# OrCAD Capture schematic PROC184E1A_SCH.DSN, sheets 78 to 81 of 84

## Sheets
78 82.CURRENT MONITORS#1 -INA231: size C; title: CURRENT MONITORS#1- INA231; note: PROC184_SCH
79 83. CURRENT MONITORS#2 -INA231: size C; title: CURRENT MONITORS#2- INA231; note: PROC184_SCH
80 84. HARDWARE SCHEMATICS: title: HARDWARE SCHEMATICS; note: PROC184_SCH
81 55. CAN TRANSCEIVER #3: size C; title: CAN TRANSCEIVER #3; note: PROC184_SCH
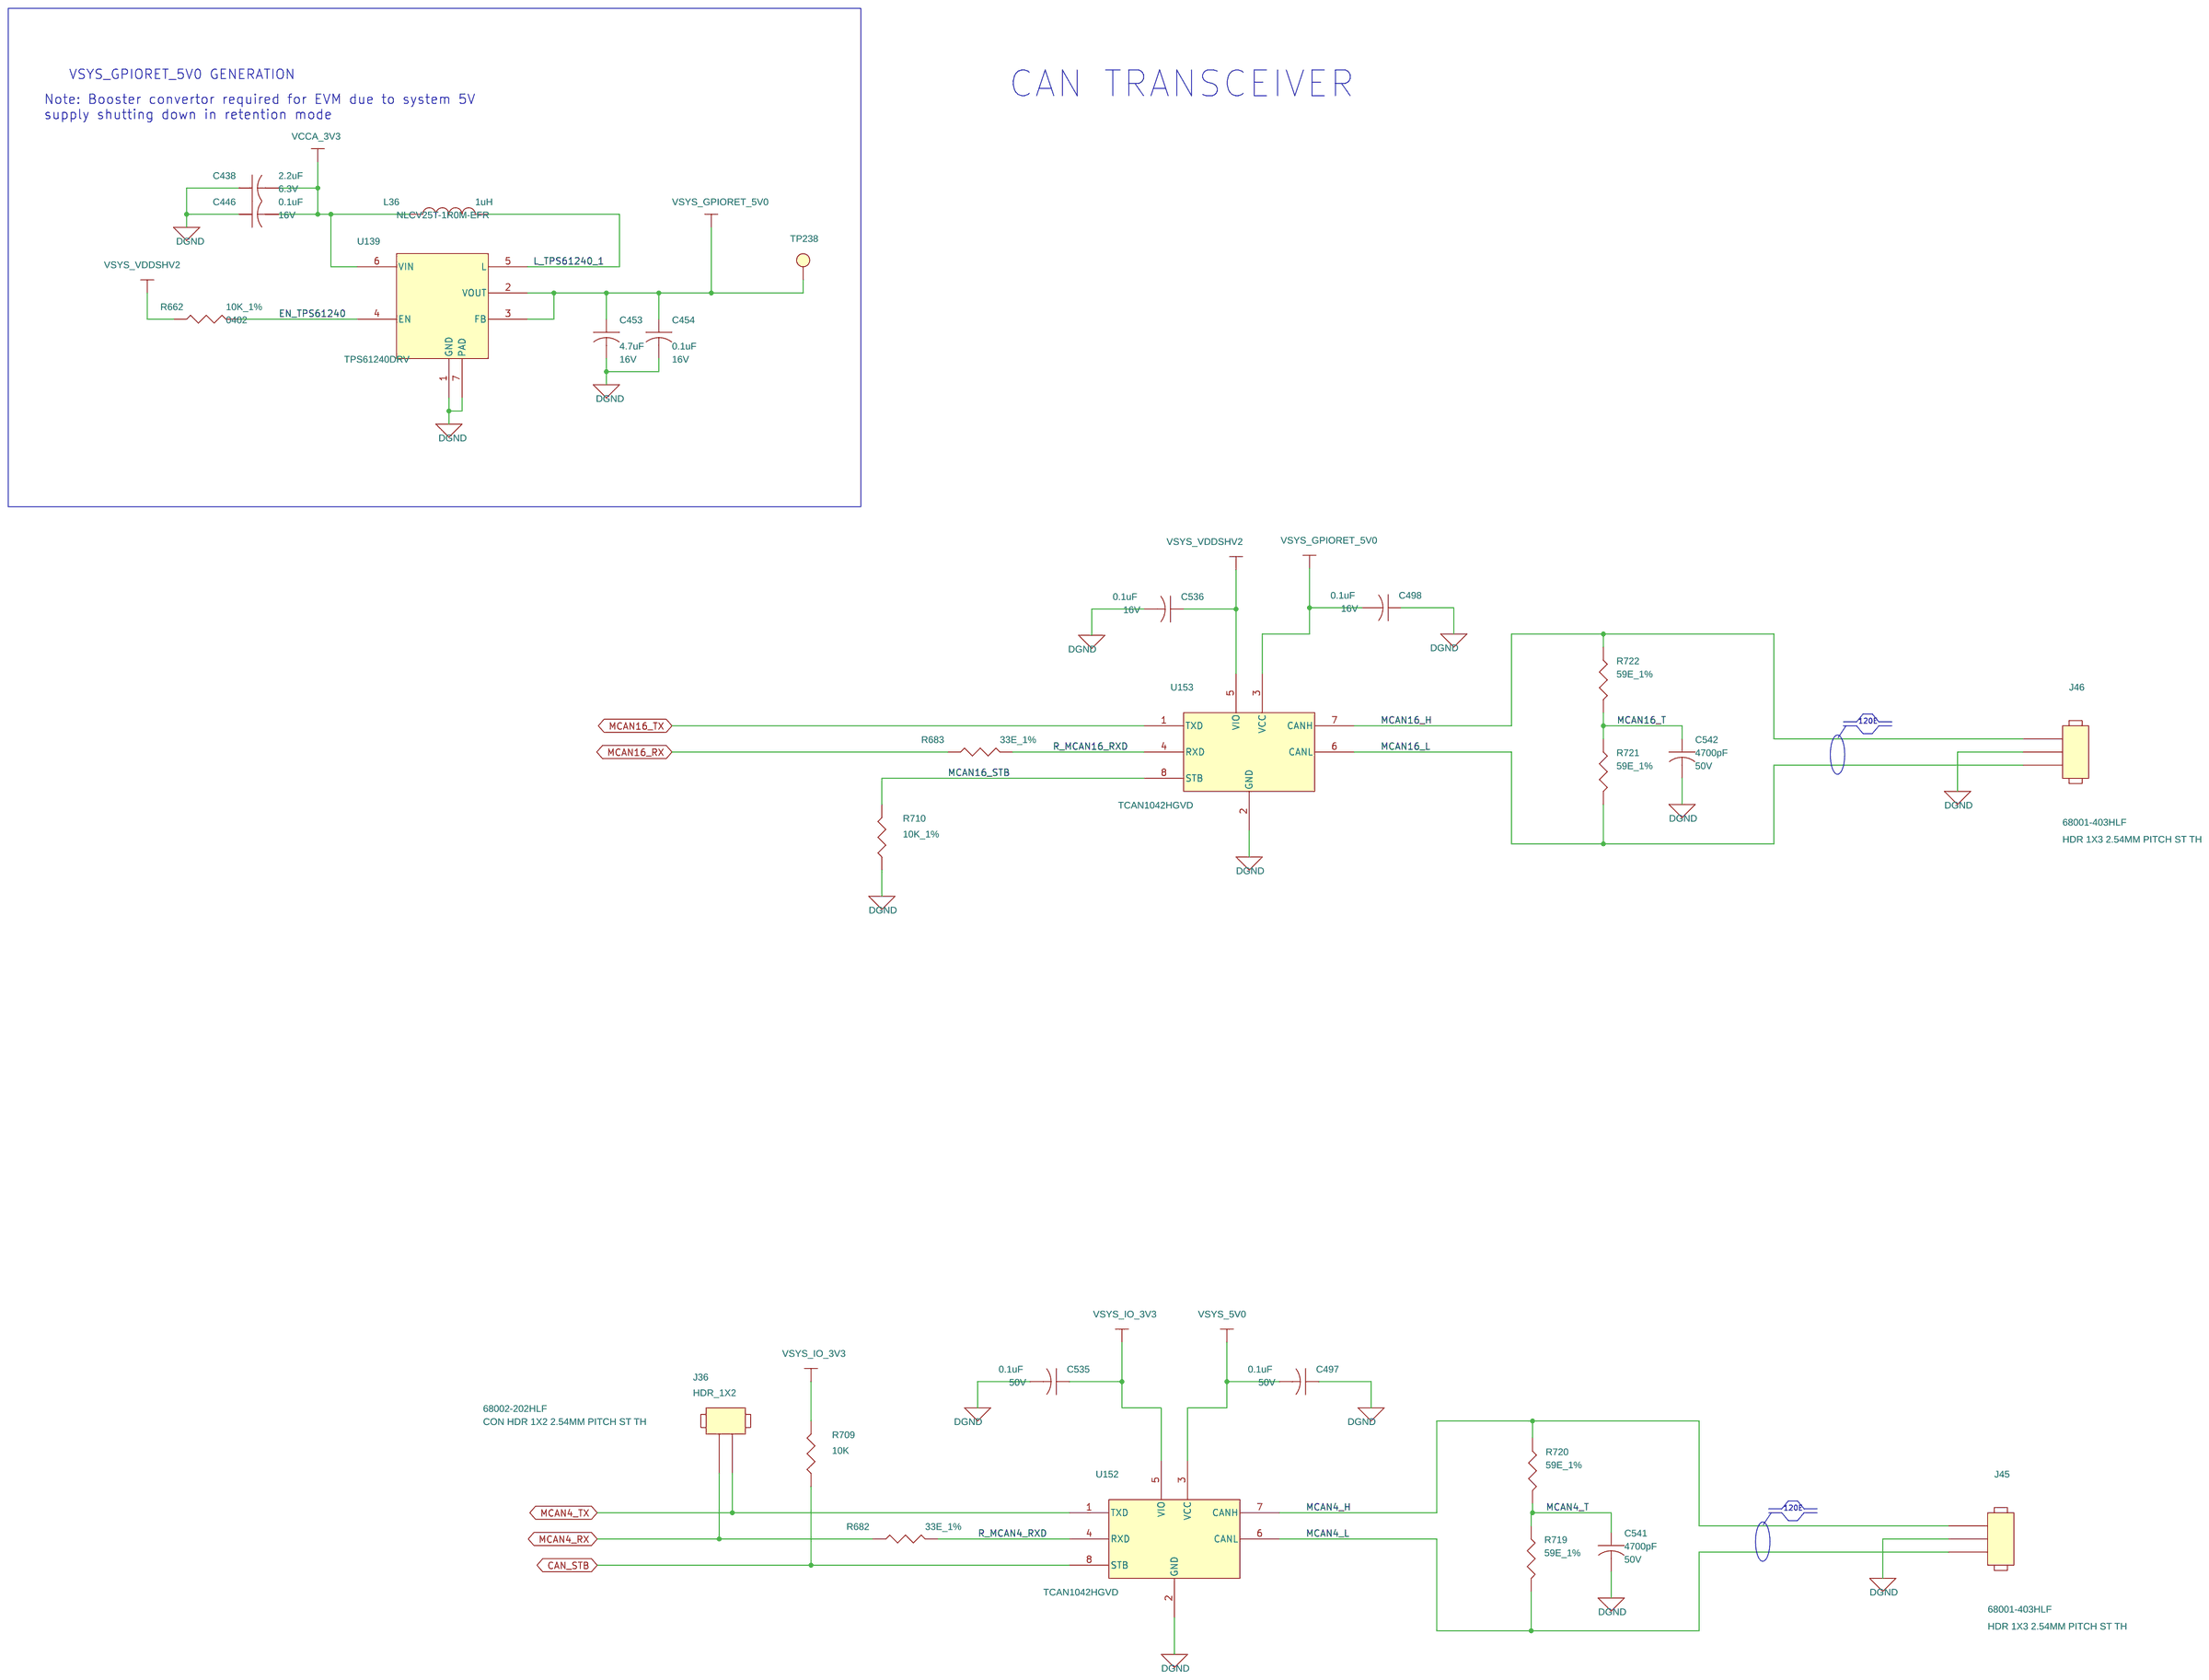
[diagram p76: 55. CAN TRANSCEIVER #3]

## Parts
sheet 55. CAN TRANSCEIVER #3
C438  2.2uF  [CAP0603_1]
C446  0.1uF  [CAP0402_0-75]
C453  4.7uF  [CAP0805_1-5]
C454  0.1uF  [CAP0402_0-75]
C497  0.1uF  [CAP0402_0-75]
C498  0.1uF  [CAP0402_0-75]
C535  0.1uF  [CAP0402_0-75]
C536  0.1uF  [CAP0402_0-75]
C541  4700pF  [CAP0402_0-75]
C542  4700pF  [CAP0402_0-75]
J36  HDR_1X2  [HDR_1X2_68002-202_S_T_8-6]
J45  HDR_1X3  [HDR_3X1_100_S_T]
J46  HDR_1X3  [HDR_3X1_100_S_T]
L36  1uH  [IND_NLCV25T-EFR_110X80_SMD_1-9]
R662  10K_1%  [RES0402_0-5]
R682  33E_1%  [RES0402_0-5]
R683  33E_1%  [RES0402_0-5]
R709  10K  [RES0402_0-5]
R710  10K_1%  [RES0402_0-5]
R719  59E_1%  [RES0402_0-5]
R720  59E_1%  [RES0402_0-5]
R721  59E_1%  [RES0402_0-5]
R722  59E_1%  [RES0402_0-5]
TP238  TP30_SMD  [TP30_SMD]
U139  TPS61240DRV  [SON6_25-59_85X85]
U152  TCAN1042HGVD  [SOIC8_1-8]
U153  TCAN1042HGVD  [SOIC8_1-8]
sheet 82.CURRENT MONITORS#1 -INA231
U61  INA231AIYFDR  [DSBGA12_15-74_60X70_0-4]
U64  INA231AIYFDR  [DSBGA12_15-74_60X70_0-4]
U84  INA231AIYFDR  [DSBGA12_15-74_60X70_0-4]
U105  INA231AIYFDR  [DSBGA12_15-74_60X70_0-4]
U114  INA231AIYFDR  [DSBGA12_15-74_60X70_0-4]
U119  INA231AIYFDR  [DSBGA12_15-74_60X70_0-4]
U185  INA231AIYFDR  [DSBGA12_15-74_60X70_0-4]
U188  INA231AIYFDR  [DSBGA12_15-74_60X70_0-4]
U192  INA231AIYFDR  [DSBGA12_15-74_60X70_0-4]
U194  INA231AIYFDR  [DSBGA12_15-74_60X70_0-4]
U198  INA231AIYFDR  [DSBGA12_15-74_60X70_0-4]
U207  INA231AIYFDR  [DSBGA12_15-74_60X70_0-4]
U225  INA231AIYFDR  [DSBGA12_15-74_60X70_0-4]
U230  INA231AIYFDR  [DSBGA12_15-74_60X70_0-4]
U231  INA231AIYFDR  [DSBGA12_15-74_60X70_0-4]
U235  INA231AIYFDR  [DSBGA12_15-74_60X70_0-4]
sheet 83. CURRENT MONITORS#2 -INA231
U31  INA231AIYFDR  [DSBGA12_15-74_60X70_0-4]
U57  INA231AIYFDR  [DSBGA12_15-74_60X70_0-4]
U93  INA231AIYFDR  [DSBGA12_15-74_60X70_0-4]
U99  INA231AIYFDR  [DSBGA12_15-74_60X70_0-4]
U116  INA231AIYFDR  [DSBGA12_15-74_60X70_0-4]
U121  INA231AIYFDR  [DSBGA12_15-74_60X70_0-4]
U129  INA231AIYFDR  [DSBGA12_15-74_60X70_0-4]
U171  INA231AIYFDR  [DSBGA12_15-74_60X70_0-4]
U204  INA231AIYFDR  [DSBGA12_15-74_60X70_0-4]
U210  INA231AIYFDR  [DSBGA12_15-74_60X70_0-4]
U211  INA231AIYFDR  [DSBGA12_15-74_60X70_0-4]
U214  INA231AIYFDR  [DSBGA12_15-74_60X70_0-4]
U219  INA231AIYFDR  [DSBGA12_15-74_60X70_0-4]
U222  INA231AIYFDR  [DSBGA12_15-74_60X70_0-4]
U223  INA231AIYFDR  [DSBGA12_15-74_60X70_0-4]
U238  INA231AIYFDR  [DSBGA12_15-74_60X70_0-4]
sheet 84. HARDWARE SCHEMATICS
ACC1  C23103  [BGASKT1063_C23103_1270X1270_11-4]
ACC2  374724B00035G  [NA]
ACC3  XJ742S2GAAND  [NA]
ACC4  CFM-4010V-170-273-20  [NA]
ACC5  NA  [NA]
ACC6  NA  [NA]
ACC7  NA  [NA]
FID1  FID_40X80  [FID_40X80]
FID2  FID_40X80  [FID_40X80]
FID3  FID_40X80  [FID_40X80]
FID4  FID_40X80  [FID_40X80]
FID5  FID_40X80  [FID_40X80]
FID6  FID_40X80  [FID_40X80]
LBL1  AM6-COMPROCEVM  [NA]
LBL2  AM6-COMPROCEVM  [NA]
LBL3  AM6-COMPROCEVM  [NA]
LOGO1  Texas Intruments  [TI_Stacked_Overlay_Small]
LOGO2  For Evaluation only; not FCC approved for resale  [FCC_disclaimer]
LOGO3  WEEE Mark  [TI_Stacked_Overlay_Small]
LOGO4  CE Mark  [TI_Stacked_Overlay_Small]
M1  728  [NA]
M2  728  [NA]
M3  728  [NA]
M4  728  [NA]
M5  728  [NA]
M6  728  [NA]
M7  728  [NA]
M8  728  [NA]
MH2  HEX SPACER_M3 X 30  [NA]
MH3  HEX SPACER_M3 X 30  [NA]
MH4  HEX SPACER_M3 X 30  [NA]
MH5  HEX SPACER_M3 X 30  [NA]
MH6  HEX SPACER_M3 X 30  [NA]
MH7  HEX SPACER_M3 X 30  [NA]
MH8  HEX SPACER_M3 X 30  [NA]
MH9  HEX SPACER_M3 X 30  [NA]
MH10  PAN HEAD_M3 X 8  [NA]
MH11  PAN HEAD_M3 X 8  [NA]
MH12  PAN HEAD_M3 X 8  [NA]
MH13  PAN HEAD_M3 X 8  [NA]
MH14  PAN HEAD_M3 X 8  [NA]
MH15  PAN HEAD_M3 X 8  [NA]
MH16  PAN HEAD_M3 X 8  [NA]
MH17  PAN HEAD_M3 X 8  [NA]
MH18  HEX SPACER_M3 X 5  [NA]
MH19  HEX SPACER_M3 X 5  [NA]
MH20  HEX SPACER_M3 X 5  [NA]
MH21  HEX SPACER_M3 X 5  [NA]
MH22  HEX SPACER_M3 X 5  [NA]
MH23  HEX SPACER_M3 X 5  [NA]
MH24  HEX SPACER_M3 X 5  [NA]
MH25  HEX SPACER_M3 X 15  [NA]
MH26  HEX SPACER_M3 X 15  [NA]
MH27  HEX SPACER_M3 X 15  [NA]
MH28  HEX SPACER_M3 X 15  [NA]
MH29  HEX SPACER_M3 X 15  [NA]
MH30  HEX SPACER_M3 X 15  [NA]
MH31  HEX SPACER_M3 X 15  [NA]
MH32  HEX SPACER_M3 X 15  [NA]
MH33  HEX SPACER_M3 X 5  [NA]
MH34  NA  [NA]
MH35  NA  [NA]
MH36  NA  [NA]
MH37  NA  [NA]
PCB1  PROC184E1

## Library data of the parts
C438 = CAP: CAP CERAMIC 2.2uF 6.3V 10% X7R AUTO 0603; Automotive Alternate_mfr_name: TDK; Automotive Alternate_mfr_part_number: CGA3E1X7R0J225K080AC; Chkd/date: MANIRAJA/050419; Crtd /date: ALVY/050419; Custom_Duty: 15%; Customs_HS_Code: 85322990; Direct Alternate_mfr_name: TDK; Direct Alternate_mfr_part_number: CGA3E1X7R0J225K080AC; Distributor_name: DIGIKEY; Distributor_part_number: 490-5316-1-ND; Footprint Path: Y:\MIS_DATABASE\Library\ALTIUM_TOOL\PCB_FOOTPRINTS\Altium_Footprint_Lib.PcbLib; Height: 0.90MM; Library Path: Y:\MIS_DATABASE\Library\ALTIUM_TOOL\SCHEMATICS_PARTS\MS_DISCRETE_Library.schlib; Manufacturer: MURATA; Mfr_name: MURATA; Mfr_part_number: GCM188R70J225KE22D; Mistral Part No: 120019040009-R; Package: 0603; Part_type: CAPACITORS\CERAMIC; Project: J7ES_SOM_DUAL-LEO_PMIC; RoHS: RoHS; Temperature: -55°C+125°C; Tolerance: 10%; Voltage: 6.3V; Wattage: NA; Weight: 6.3mg; Datasheet: Y:\MIS_DATABASE\DATASHEETS\CAPACITORS\GCM188R70J225KE22.PDF
C446 C454 C498 C536 = CAP: CAP CERAMIC 0.1uF 16V 10% X7R AUTO 0402; Automotive Alternate_mfr_name: TDK; Automotive Alternate_mfr_part_number: CGA2B1X7R1C104K050BC; Chkd/date: NAVEED/021014; Crtd /date: VASANTHA/300514; Custom_Duty: 15%; Customs_HS_Code: 85322990; Direct Alternate_mfr_name: MURATA; Direct Alternate_mfr_part_number: GCM155R71C104JA55D; Distributor_name: DIGIKEY; Distributor_part_number: 490-4759-1-ND; Footprint Path: Y:\MIS_DATABASE\Library\ALTIUM_TOOL\PCB_FOOTPRINTS\Altium_Footprint_Lib.PcbLib; Height: 0.55MM; Library Path: Y:\MIS_DATABASE\Library\ALTIUM_TOOL\SCHEMATICS_PARTS\MS_DISCRETE_Library.schlib; Manufacturer: MURATA; Mfr_name: MURATA; Mfr_part_number: GCM155R71C104KA55D; Mistral Part No: 120016070006-R; Package: 0402; Part_type: CAPACITORS\CERAMIC; Project: DCMIST_FPGA_CARD; RoHS: RoHS; Temperature: -55°C+125°C; Tolerance: 10%; Voltage: 16V; Wattage: NA; Weight: 6mg; Datasheet: Y:\MIS_DATABASE\DATASHEETS\CAPACITORS\MURATA-GCM-SER.PDF
C453 = CAP: CAP CERAMIC 4.7uF 16V 10% X7R AUTO 0805; Chkd/date: MANIRAJA/011018; Crtd /date: MANIRAJA/011018; Custom_Duty: 15%; Customs_HS_Code: 85322990; Distributor_name: DIGIKEY; Distributor_part_number: 490-14532-1-ND; Footprint Path: Y:\MIS_DATABASE\Library\ALTIUM_TOOL\PCB_FOOTPRINTS\Altium_Footprint_Lib.PcbLib; Height: 1.40MM; Library Path: Y:\MIS_DATABASE\Library\ALTIUM_TOOL\SCHEMATICS_PARTS\MS_DISCRETE_Library.schlib; Manufacturer: MURATA; Mfr_name: MURATA; Mfr_part_number: GCM21BR71C475KA73K; Mistral Part No: 120018100002-R; Package: 0805; Part_type: CAPACITORS\CERAMIC; Project: TI_J7_SVB-DUT; RoHS: RoHS; Temperature: -55°C+125°C; Tolerance: 10%; Voltage: 16V; Wattage: NA; Weight: 9.5mg; Datasheet: Y:\MIS_DATABASE\DATASHEETS\CAPACITORS\GCM21BR71C475KA73.PDF
C497 C535 = CAP: CAP CERAMIC 0.1uF 50V 10% X7R 0402; Automotive Alternate_mfr_name: TDK; Automotive Alternate_mfr_part_number: CGA2B3X7R1H104K050BB; Chkd/date: MANIRAJA/261020; Crtd /date: ALVY/211020; Custom_Duty: 15%; Customs_HS_Code: 85322990; Direct Alternate_mfr_name: TDK; Direct Alternate_mfr_part_number: C1005X7R1H104K050BE; Distributor_name: DIGIKEY; Distributor_part_number: 490-10700-1-ND; Footprint Path: Y:\MIS_DATABASE\Library\ALTIUM_TOOL\PCB_FOOTPRINTS\Altium_Footprint_Lib.PcbLib; Height: 0.55MM; Library Path: Y:\MIS_DATABASE\Library\ALTIUM_TOOL\SCHEMATICS_PARTS\MS_DISCRETE_Library.schlib; Manufacturer: MURATA; Mfr_name: MURATA; Mfr_part_number: GRM155R71H104KE14D; Mistral Part No: 120011100014-R; Package: 0402; Part_type: CAPACITORS\CERAMIC; Project: J7_CP; RoHS: RoHS; Temperature: -55°C+125°C; Tolerance: 10%; Voltage: 50V; Wattage: NA; Weight: 3.1mg; Datasheet: Y:\MIS_DATABASE\DATASHEETS\CAPACITORS\GRM155R71H104KE14.PDF
C541 C542 = CAP: CAP CERAMIC 4700pF 50V 5% X7R 0402; Automotive Alternate_mfr_name: TDK; Automotive Alternate_mfr_part_number: CGA2B2X7R1H472K050BA; Chkd/date: MANIRAJA/070619; Crtd /date: MANIRAJA/070619; Custom_Duty: 15%; Customs_HS_Code: 85322990; Direct Alternate_mfr_name: SAMSUNG; Direct Alternate_mfr_part_number: CL05B472KB5NNNC; Distributor_name: DIGIKEY; Distributor_part_number: 478-5767-1-ND; Footprint Path: Y:\MIS_DATABASE\Library\ALTIUM_TOOL\PCB_FOOTPRINTS\Altium_Footprint_Lib.PcbLib; Height: 0.56MM; Library Path: Y:\MIS_DATABASE\Library\ALTIUM_TOOL\SCHEMATICS_PARTS\MS_DISCRETE_Library.schlib; Manufacturer: AVX CORPORATION; Mfr_name: AVX CORPORATION; Mfr_part_number: 04025C472JAT2A; Mistral Part No: 120013090022-R; Package: 0402; Part_type: CAPACITORS\CERAMIC; Project: J7ES_SOM_DUAL-LEO_PMIC; RoHS: RoHS; Temperature: -55°C+125°C; Tolerance: 5%; Voltage: 50V; Wattage: NA; Weight: 0.65mg; Datasheet: Y:\MIS_DATABASE\DATASHEETS\CAPACITORS\AVX_MLC.PDF
J36 = HEADER_2X1: CON HDR 1X2 2.54MM PITCH ST TH; Chkd/date: MANIRAJA/190118; Crtd /date: ALVY/190118; Custom_Duty: 24%; Customs_HS_Code: 85369090; Distributor_name: DIGIKEY; Distributor_part_number: 68002-202HLF-ND; Height: 8.58MM; Manufacturer: AMPHENOL; Mfr_name: AMPHENOL; Mfr_part_number: 68002-202HLF; Mistral Part No: 150018010012-R; Package: THRU HOLE; Part_type: CONNECTOR\HEADERS; Project: TI_SVB_MAXWELL_DUT; RoHS: RoHS; Temperature: NA; Tolerance: NA; Voltage: NA; Wattage: NA; Weight: NA; Datasheet: Y:\MIS_DATABASE\DATASHEETS\CONNECTORS\68002.PDF
J45 J46 = HEADER_3X1: HDR 1X3 2.54MM PITCH ST TH; Chkd/date: VASANTHA/290616; Crtd /date: VASANTHA/290616; Custom_Duty: 15%; Customs_HS_Code: 85322990; Distributor_name: DIGIKEY; Distributor_part_number: 609-3471-ND; Height: 8.58MM; Manufacturer: FCI; Mfr_name: FCI; Mfr_part_number: 68001-403HLF; Mistral Part No: 150016060025-R; Package: THRU-HOLE; Part_type: CONNECTOR\HEADERS; Project: IKEYP; RoHS: RoHS; Temperature: -40°C+105°C; Tolerance: NA; Voltage: NA; Wattage: NA; Weight: NA; Datasheet: Y:\MIS_DATABASE\DATASHEETS\CONNECTORS\68000.PDF
L36 = INDUCTOR: IND POWER 1uH 1A 20% SMD; Automotive Alternate_mfr_name: TDK; Automotive Alternate_mfr_part_number: NLCV25T-1R0M-EFRD; Chkd/date: MANIRAJA/161118; Crtd /date: ALVY/161118; Custom_Duty: 24%; Customs_HS_Code: 85369090; Direct Alternate_mfr_name: TDK; Direct Alternate_mfr_part_number: NLCV25T-1R0M-EFR; Distributor_name: DIGIKEY; Distributor_part_number: 445-17087-1-ND; Footprint Path: Y:\MIS_DATABASE\Library\ALTIUM_TOOL\PCB_FOOTPRINTS\Altium_Footprint_Lib.PcbLib; Height: 1.90MM; Library Path: Y:\MIS_DATABASE\Library\ALTIUM_TOOL\SCHEMATICS_PARTS\MS_DISCRETE_Library.schlib; Manufacturer: TDK CORPORATION; Mfr_name: TDK CORPORATION; Mfr_part_number: NLCV25T-1R0M-EFR; Mistral Part No: 130018110021-R; Package: SMD; Project: TI_J7ES_EVM_CP; RoHS: RoHS; Temperature: -40°C+125°C; Tolerance: 20%; Voltage: NA; Wattage: NA; Weight: 25mg; Datasheet: Y:\MIS_DATABASE\DATASHEETS\DISCRETES\INDUCTORS\NLCV25T-EFR.PDF
R662 = RESISTOR: RES 10K 1/16W 1% 0402; Assembly_Instruction: DNI; Chkd/date: VASANTHA/201216; Crtd /date: GEETHA/290506; Custom_Duty: 15%; Customs_HS_Code: 85332119; Distributor_name: DIGIKEY; Distributor_part_number: 311-10.0KLRTR-ND; Footprint Path: Y:\MIS_DATABASE\Library\ALTIUM_TOOL\PCB_FOOTPRINTS\Altium_Footprint_Lib.PcbLib; Height: 0.40MM; Library Path: Y:\MIS_DATABASE\Library\ALTIUM_TOOL\SCHEMATICS_PARTS\MS_DISCRETE_Library.schlib; Manufacturer: YAGEO AMERICA; Mfr_name: YAGEO AMERICA; Mfr_part_number: RC0402FR-0710KL; Mistral Part No: 110015090015-R; Package: 0402; Part_type: RESISTORS\FIXED; Project: VOCERA; RoHS: RoHS; Temperature: -55°C+155°C; Tolerance: 1%; Voltage: NA; Wattage: 1/16W; Weight: 0.65mg; Datasheet: Y:\MIS_DATABASE\DATASHEETS\RESISTORS\RCXXXXL-SER_MAR18.PDF
R682 R683 = RESISTOR: RES 33E 1/10W 1% 0402; Chkd/date: VASANTHA/061216; Crtd /date: JEBRAN/171114; Custom_Duty: 15%; Customs_HS_Code: 85332119; Distributor_name: DIGIKEY; Distributor_part_number: P33.0LCT-ND; Footprint Path: Y:\MIS_DATABASE\Library\ALTIUM_TOOL\PCB_FOOTPRINTS\Altium_Footprint_Lib.PcbLib; Height: 0.40MM; Library Path: Y:\MIS_DATABASE\Library\ALTIUM_TOOL\SCHEMATICS_PARTS\MS_DISCRETE_Library.schlib; Manufacturer: PANASONIC-ECG; Mfr_name: PANASONIC-ECG; Mfr_part_number: ERJ-2RKF33R0X; Mistral Part No: 110014110006-R; Package: 0402; Part_type: RESISTORS\FIXED; Project: ZK BIOMETRIC; RoHS: RoHS; Temperature: -55°C+155°C; Tolerance: 1%; Voltage: NA; Wattage: 1/10W; Weight: 0.8mg; Datasheet: Y:\MIS_DATABASE\DATASHEETS\RESISTORS\PAN-ERJSER_NOV17.PDF
R709 = RESISTOR: RES 10K 1/16W 5% 0402; Chkd/date: VASANTHA/061216; Crtd /date: MAZHAR/230805; Custom_Duty: 15%; Customs_HS_Code: 85332119; Distributor_name: DIGIKEY; Distributor_part_number: 311-10KJRCT-ND; Footprint Path: Y:\MIS_DATABASE\Library\ALTIUM_TOOL\PCB_FOOTPRINTS\Altium_Footprint_Lib.PcbLib; Height: 0.40MM; Library Path: Y:\MIS_DATABASE\Library\ALTIUM_TOOL\SCHEMATICS_PARTS\MS_DISCRETE_Library.schlib; Manufacturer: YAGEO AMERICA; Mfr_name: YAGEO AMERICA; Mfr_part_number: RC0402JR-0710KL; Mistral Part No: 110011060021-R; Package: 0402; Part_type: RESISTORS\FIXED; Project: HSE; RoHS: RoHS; Temperature: -55°C+155°C; Tolerance: 5%; Voltage: NA; Wattage: 1/16W; Weight: 0.65mg; Datasheet: Y:\MIS_DATABASE\DATASHEETS\RESISTORS\RCXXXXL-SER_MAR18.PDF
R710 = RESISTOR: RES 10K 1/16W 1% 0402; Chkd/date: VASANTHA/201216; Crtd /date: GEETHA/290506; Custom_Duty: 15%; Customs_HS_Code: 85332119; Distributor_name: DIGIKEY; Distributor_part_number: 311-10.0KLRTR-ND; Footprint Path: Y:\MIS_DATABASE\Library\ALTIUM_TOOL\PCB_FOOTPRINTS\Altium_Footprint_Lib.PcbLib; Height: 0.40MM; Library Path: Y:\MIS_DATABASE\Library\ALTIUM_TOOL\SCHEMATICS_PARTS\MS_DISCRETE_Library.schlib; Manufacturer: YAGEO AMERICA; Mfr_name: YAGEO AMERICA; Mfr_part_number: RC0402FR-0710KL; Mistral Part No: 110015090015-R; Package: 0402; Part_type: RESISTORS\FIXED; Project: VOCERA; RoHS: RoHS; Temperature: -55°C+155°C; Tolerance: 1%; Voltage: NA; Wattage: 1/16W; Weight: 0.65mg; Datasheet: Y:\MIS_DATABASE\DATASHEETS\RESISTORS\RCXXXXL-SER_MAR18.PDF
R719-R722 = RESISTOR: RES 59E 1/10W 1% 0402; Chkd/date: MAZHAR/151208; Crtd /date: USMAN/031208; Custom_Duty: 15%; Customs_HS_Code: 85332119; Distributor_name: DIGIKEY; Distributor_part_number: P59.0LCT-ND; Footprint Path: Y:\MIS_DATABASE\Library\ALTIUM_TOOL\PCB_FOOTPRINTS\Altium_Footprint_Lib.PcbLib; Height: 0.40MM; Library Path: Y:\MIS_DATABASE\Library\ALTIUM_TOOL\SCHEMATICS_PARTS\MS_DISCRETE_Library.schlib; Manufacturer: PANASONIC-ECG; Mfr_name: PANASONIC-ECG; Mfr_part_number: ERJ-2RKF59R0X; Mistral Part No: 110009031010-R; Package: 0402; Part_type: RESISTORS\FIXED; Project: KHAN_HSST; RoHS: RoHS; Temperature: -55°C+155°C; Tolerance: 1%; Voltage: NA; Wattage: 1/10W; Weight: 0.8mg; Datasheet: Y:\MIS_DATABASE\DATASHEETS\RESISTORS\PAN-ERJSER_NOV17.PDF
TP238 = TESTPOINT: TESTPOINT CIR 30 SMD; Chkd/date: SHREESHAIL/171006; Crtd /date: MAZHAR/171006; Custom_Duty: NA; Customs_HS_Code: NA; Distributor_name: NA; Distributor_part_number: NA; Footprint Path: Y:\MIS_DATABASE\Library\ALTIUM_TOOL\PCB_FOOTPRINTS\Altium_Footprint_Lib.PcbLib; Height: NA; Library Path: Y:\MIS_DATABASE\Library\ALTIUM_TOOL\SCHEMATICS_PARTS\MS_DISCRETE_Library.schlib; MECHANICAL 3D STEP FILE: NA; Manufacturer: LOCAL; Mfr_name: LOCAL; Mistral Part No: 130009030930; Package: SMD; Project: BT MODULE_CSRBC04; RoHS: NA; Temperature: NA; Tolerance: NA; Voltage: NA; Wattage: NA; Weight: NA; Datasheet: NA
U139 = TPS61240DRV_SON6: IC CONV STEP-UP 400MA DC/DC SON6; Automotive Alternate_mfr_name: TEXAS INSTRUMENTS; Automotive Alternate_mfr_part_number: TPS61240IDRVRQ1; Chkd/date: SUHAS/211010; Crtd /date: MAZHAR/240909; Custom_Duty: 15%; Customs_HS_Code: 85423100; Distributor_name: DIGIKEY; Distributor_part_number: 296-24519-1-ND; Footprint Path: Y:\MIS_DATABASE\Library\ALTIUM_TOOL\PCB_FOOTPRINTS\Altium_Footprint_Lib.PcbLib; Height: 0.80MM; Library Path: Y:\MIS_DATABASE\Library\ALTIUM_TOOL\SCHEMATICS_PARTS\MS_MISCPOWER_Library.schlib; Manufacturer: TEXAS INSTRUMENTS; Mfr_name: TEXAS INSTRUMENTS; Mistral Part No: 142009090013-P; Package: SON6; Part_type: ICS\POWER\DC-DC CONVERTER; Project: GOLDEN-I; RoHS: Sb/ Br FREE; Temperature: -40°C+85°C; Tolerance: NA; Voltage: NA; Wattage: NA; Datasheet: Y:\MIS_DATABASE\DATASHEETS\ICS\POWER\TPS6124.PDF
U152 U153 = TCAN1042HGVD_SOIC8: IC FAULT PROTECTED CAN TRANSCEIVER WITH CAN FD SOIC8; Automotive Alternate_mfr_name: TEXAS INSTRUMENTS; Automotive Alternate_mfr_part_number: TCAN1042HGV-Q1; Chkd/date: MANIRAJA/030717; Crtd /date: MANIRAJA/030717; Custom_Duty: 15%; Customs_HS_Code: 85423100; Distributor_name: DIGIKEY; Distributor_part_number: 296-43979-5-ND; Footprint Path: Y:\MIS_DATABASE\Library\ALTIUM_TOOL\PCB_FOOTPRINTS\Altium_Footprint_Lib.PcbLib; Height: 1.75MM; Library Path: Y:\MIS_DATABASE\Library\ALTIUM_TOOL\SCHEMATICS_PARTS\MS_TELECOM_Library.schlib; Manufacturer: TEXAS INSTRUMENTS; Mfr_name: TEXAS INSTRUMENTS; Mistral Part No: 143017070001-R; Package: SOIC8; Part_type: ICS\TELECOM\TRANSCEIVER; Project: TI_SVB_CONTROLLER CARD; RoHS: RoHS; Temperature: -55°C+125°C; Tolerance: NA; Voltage: NA; Wattage: NA; Weight: 540mg; Datasheet: Y:\MIS_DATABASE\DATASHEETS\ICS\DIGITAL\BUSTRANSCEIVER\TCAN1042.PDF
U31 U57 U61 U64 U84 U93 U99 U105 U114 U116 U119 U121 U129 U171 U185 U188 U192 U194 U198 U204 U207 U210 U211 U214 U219 U222 U223 U225 U230 U231 U235 U238 = INA231_DSBGA12: IC HIGH OR LOW SIDE MEASUREMENT BI-DIR CURRENT AND POWER MONITOR WITH 1.8V I2C INTERFACE DSBGA12; Chkd/date: MANIRAJA/250821; Crtd /date: ALVY/250821; Custom_Duty: 15%; Customs_HS_Code: 85423100; Distributor_name: DIGIKEY; Distributor_part_number: 296-49645-1-ND; Footprint Path: Y:\MIS_DATABASE\Library\ALTIUM_TOOL\PCB_FOOTPRINTS\Altium_Footprint_Lib.PcbLib; Height: 0.40MM; Library Path: Y:\MIS_DATABASE\Library\ALTIUM_TOOL\SCHEMATICS_PARTS\MS_MISCPOWER_Library.schlib; Manufacturer: TEXAS INSTRUMENTS; Mfr_name: TEXAS INSTRUMENTS; Mistral Part No: 142021080022-R; Package: DSBGA12; Part_type: ICS\POWER\MANAGEMENT; Project: TI_AM62x SVB_BRD; RoHS: RoHS; Temperature: -40°C+125°C; Tolerance: NA; Voltage: NA; Wattage: NA; Weight: 200mg; Datasheet: Y:\MIS_DATABASE\DATASHEETS\ICS\POWER\INA231XXX.PDF
ACC1 = ACCESSORY: ACCESSORIE BGA SOCKET MICROPROCESSOR BGA1063; Chkd/date: PRADEEP/160124; Crtd /date: TAMILARASU/160124; Custom_Duty: NA; Customs_HS_Code: NA; Distributor_name: NA; Distributor_part_number: NA; Footprint Path: NA; Height: 11.40MM; Library Path: NA; Mfr_name: IRONWOOD ELECTRONICS; Mistral Part No: 160024010010; Package: BGA1063; Part_type: ACCESSORIES; Project: J7AHP27; RoHS: NA; Temperature: NA; Tolerance: NA; Voltage: NA; Wattage: NA; Weight: 46.87mg; Datasheet: Y:\MIS_DATABASE\DATASHEETS\MISC\ACCESSORIES\C23103.PDF
ACC2 = ACCESSORY: HEATSINK BGA 35X35X18MM W/ADH; Chkd/date: MANIRAJA/280920; Crtd /date: ALVY/281018; Mfr_name: Aavid, Thermal Division of Boyd Corporation; Part_type: ACCESSORIES; Project: TI_J7AHP; RoHS: RoHS; Datasheet: Y:\MIS_DATABASE\DATASHEETS\MISC\ACCESSORIES\374424BXXXXG-SER.PDF
ACC3 = ACCESSORY: IC J7AHP SoC EVM MICROPROCESSOR BGA1414; Chkd/date: MANIRAJA/280920; Crtd /date: ALVY/281018; Distributor_part_number: XJ784S4GAALY; Part_type: ACCESSORIES; Project: TI_J7AHP; RoHS: RoHS; Datasheet: Y:\MIS_DATABASE\DATASHEETS\MISC\ACCESSORIES\374424BXXXXG-SER.PDF
ACC4 = ACCESSORY: Fan Tubeaxial 12VDC Square - 40mm L x 40mm H omniCOOL™ Magnetic Sleeve 8.0 CFM (0.224m³/min) 3 Wire Leads; Chkd/date: MANIRAJA/280920; Crtd /date: ALVY/281018; Mfr_name: CUI Devices; Part_type: ACCESSORIES; Project: TI_J7AHP; RoHS: RoHS; Datasheet: Y:\MIS_DATABASE\DATASHEETS\MISC\ACCESSORIES\374424BXXXXG-SER.PDF
ACC5 ACC6 = ACCESSORY: CONN SOCKET 24-30AWG CRIMP TIN; Chkd/date: MANIRAJA/280920; Crtd /date: ALVY/281018; Distributor_part_number: 1735801-1; Mfr_name: TE Connectivity AMP Connectors; Mfr_part_number: 1735801-1; Part_type: ACCESSORIES; Project: TI_J7AHP; RoHS: RoHS; Datasheet: Y:\MIS_DATABASE\DATASHEETS\MISC\ACCESSORIES\374424BXXXXG-SER.PDF
ACC7 = ACCESSORY: 3 Rectangular Connectors - Housings Receptacle Natural 0.079" (2.00mm); Chkd/date: MANIRAJA/280920; Crtd /date: ALVY/281018; Distributor_part_number: 440129-3; Mfr_name: TE Connectivity AMP Connectors; Mfr_part_number: 440129-3; Part_type: ACCESSORIES; Project: TI_J7AHP; RoHS: RoHS; Datasheet: Y:\MIS_DATABASE\DATASHEETS\MISC\ACCESSORIES\374424BXXXXG-SER.PDF
FID1-FID6 = Fiducial
LBL1-LBL3 = ACCESSORY_THT-3-423-10: ACCESSORIE 1 WORKHORSE POLYSTER LABLE 0.25" X 1"; Chkd/date: MANIRAJA/270218; Crtd /date: ALVY/260218; Footprint Path: Y:\MIS_DATABASE\Library\ALTIUM_TOOL\PCB_FOOTPRINTS\Altium_Footprint_Lib.PcbLib; Library Path: Y:\MIS_DATABASE\Library\ALTIUM_TOOL\SCHEMATICS_PARTS\MS_MECHANICAL_Library.schlib; Mfr_name: BRADY; Mfr_part_number: THT-103-423-10; Mistral Part No: 160018020185; Part_type: ACCESSORIES; Project: TI_MAXIE_CPB
LOGO1 LOGO3 LOGO4 = TI_Logo
LOGO2 = FCC_disclaimer
M1-M8 = ACCESSORY: ACCESSORIE RECESSED BUMPER 19.05MM DIA; Chkd/date: MANIRAJA/110718; Crtd /date: MANIRAJA/110718; Distributor_name: DIGIKEY; Distributor_part_number: 36-728-ND; Manufacturer: KEYSTONE; Mfr_name: KEYSTONE; Mistral Part No: 160018070042-R; Part_type: ACCESSORIES; Project: TI_MAXIE_CPB; RoHS: RoHS; Weight: 2042mg; Datasheet: Y:\MIS_DATABASE\DATASHEETS\MISC\ACCESSORIES\728.PDF
MH2-MH9 = HEX_SPACER_FF: HEX SPACER FEMALE TO FEMALE M3 X 30MM STEEL; Chkd/date: MANIRAJA/110319; Crtd /date: ALVY/110319; Distributor_name: DIGIKEY; Distributor_part_number: 732-10627-ND; Height: 30.00MM; Manufacturer: WURTH ELECTRONICS; Mfr_name: WURTH ELECTRONICS; Mfr_part_number: 970300321; Mistral Part No: 160019030013-R; Package: STEEL; Part_type: MECHANICAL\SPACER; Project: TI_J7ES_EVM_CP; RoHS: RoHS; Datasheet: Y:\MIS_DATABASE\DATASHEETS\MISC\MECHANICAL\970XXX1.PDF
MH10-MH17 = SCREW_PAN: PHILLIPS PAN HEAD SCREW - M3 X 8 SS-316; Chkd/date: MANIRAJA/110319; Crtd /date: ALVY/110319; Distributor_name: DIGIKEY; Distributor_part_number: 335-1149-ND; Height: 8.00MM; Manufacturer: APM; Mfr_name: APM; Mfr_part_number: RM3X8MM 2701; Mistral Part No: 160019030011-R; Package: SS; Part_type: MECHANICAL\SCREWS; Project: TI_J7ES_EVM_CP; RoHS: RoHS; Weight: 694.6mg; Datasheet: Y:\MIS_DATABASE\DATASHEETS\MISC\MECHANICAL\RM3X10MM.PDF
MH18-MH24 MH33 = HEX_SPACER_MM: HEX SPACER MALE TO MALE M3 X 5MM BRASS; Chkd/date: MANIRAJA/110319; Crtd /date: ALVY/110319; Distributor_name: DIGIKEY; Distributor_part_number: 952-2611-ND; Height: 5.00MM; Manufacturer: HARWIN; Mfr_name: HARWIN; Mfr_part_number: R30-4000502; Mistral Part No: 160019030012-R; Package: BRASS; Part_type: MECHANICAL\SPACER; Project: TI_J7ES_EVM_CP; RoHS: RoHS; Datasheet: Y:\MIS_DATABASE\DATASHEETS\MISC\MECHANICAL\R30-400XX02.PDF
MH25-MH32 = HEX_SPACER_MF: HEX SPACER MALE TO FEMALE M3 X 15MM STEEL; Chkd/date: MANIRAJA/110319; Crtd /date: ALVY/110319; Distributor_name: DIGIKEY; Distributor_part_number: 732-10415-ND; Height: 15.00MM; Manufacturer: WURTH ELECTRONICS; Mfr_name: WURTH ELECTRONICS; Mfr_part_number: 971150321; Mistral Part No: 160019030014-R; Package: STEEL; Part_type: MECHANICAL\SPACER; Project: TI_J7ES_EVM_CP; RoHS: RoHS; Datasheet: Y:\MIS_DATABASE\DATASHEETS\MISC\MECHANICAL\971XX0XX1.PDF
MH34-MH37 = SCREW_PAN: 316 Stainless Steel Pan Head Phillips Screws M3 x 0.50 mm Thread, 20mm Long; Chkd/date: MANIRAJA/110319; Crtd /date: ALVY/110319; Distributor_part_number: 90116A165; Height: 8.00MM; Manufacturer: McMaster-Carr; Mfr_name: McMaster-Carr; Mfr_part_number: 90116A165; Package: SS; Part_type: MECHANICAL\SCREWS; Project: TI_J7AHP; RoHS: RoHS; Weight: 694.6mg; Datasheet: Y:\MIS_DATABASE\DATASHEETS\MISC\MECHANICAL\RM3X10MM.PDF
PCB1 = ACCESSORY_PROC079: J7X AHP EVM BOARD REV E4 BARE PCB; Mfr_name: ANY

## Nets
DGND: C438.1 C446.1 C453.2 C454.2 C497.1 C498.1 C535.2 C536.2 C541.2 C542.2 J45.2 J46.2 R710.1 U31.C1(GND) U57.B3(A0) U57.C1(GND) U57.C3(A1) U61.B3(A0) U61.C1(GND) U61.C3(A1) U64.C1(GND) U64.C3(A1) U84.C1(GND) U93.B3(A0) U93.C1(GND) U99.C1(GND) U105.B3(A0) U105.C1(GND) U114.C1(GND) U114.C3(A1) U116.C1(GND) U119.C1(GND) U119.C3(A1) U121.C1(GND) U129.C1(GND) U129.C3(A1) U139.1(GND) U139.7(PAD) U152.2(GND) U153.2(GND) U171.B3(A0) U171.C1(GND) U185.C1(GND) U188.C1(GND) U192.C1(GND) U194.B3(A0) U194.C1(GND) U198.C1(GND) U204.C1(GND) U207.C1(GND) U210.B3(A0) U210.C1(GND) U211.C1(GND) U214.C1(GND) U214.C3(A1) U219.C1(GND) U219.C3(A1) U222.C1(GND) U223.C1(GND) U225.B3(A0) U225.C1(GND) U230.C1(GND) U231.C1(GND) U235.C1(GND) U238.C1(GND) ; also on sheet 11 12 13 14 15 16 17 18 20 21 22 23 24 25 26 27 28 29 30 31 32 33 34 35 36 37 38 39 40 41 42 43 44 45 46 47 48 49 50 51 52 53 54 55 56 57 58 59 60 61 62 63 64 65 66 67 68 69 70 71 72 73 76 77 82 83 84
VCC_12V0_IN+: U238.D3(IN+) ; also on sheet 77
VCC_12V0_IN-: U238.D1(BUS) U238.D2(IN-) ; also on sheet 77
VCCA_3V3: C438.2 C446.2 L36.1 U139.6(VIN) ; also on sheet 23 54 69 70 71 72 75
VCCA_3V3_CORE_IN+: U204.D3(IN+) ; also on sheet 77
VCCA_3V3_CORE_IN-: U204.D1(BUS) U204.D2(IN-) ; also on sheet 77
VCCA_3V3_CPU_AVS_IN+: U31.D3(IN+) ; also on sheet 77
VCCA_3V3_CPU_AVS_IN-: U31.D1(BUS) U31.D2(IN-) ; also on sheet 77
VCCA_3V3_DDR_IN+: U211.D3(IN+) ; also on sheet 77
VCCA_3V3_DDR_IN-: U211.D1(BUS) U211.D2(IN-) ; also on sheet 77
VDD1_DDR_1V8_IN+: U129.D3(IN+) ; also on sheet 77
VDD1_DDR_1V8_IN-: U129.D1(BUS) U129.D2(IN-) ; also on sheet 77
VDD_DDR_1V1_IN+: U84.D3(IN+) ; also on sheet 76
VDD_DDR_1V1_IN-: U84.D1(BUS) U84.D2(IN-) ; also on sheet 76
VDD_DDR_SOC_1V1_IN+: U93.D3(IN+) ; also on sheet 77
VDD_DDR_SOC_1V1_IN-: U93.D1(BUS) U93.D2(IN-) ; also on sheet 77
VDD_GPIORET_IO_3V3_IN+: U235.D3(IN+) ; also on sheet 76
VDD_GPIORET_IO_3V3_IN-: U235.D1(BUS) U235.D2(IN-) ; also on sheet 76
VDD_GPIORET_WK_0V8_IN+: U231.D3(IN+) ; also on sheet 76
VDD_GPIORET_WK_0V8_IN-: U231.D1(BUS) U231.D2(IN-) ; also on sheet 76
VDD_IO_1V8_IN+: U57.D3(IN+) ; also on sheet 77
VDD_IO_1V8_IN-: U57.D1(BUS) U57.D2(IN-) ; also on sheet 77
VDD_IO_3V3_IN+: U219.D3(IN+) ; also on sheet 77
VDD_IO_3V3_IN-: U219.D1(BUS) U219.D2(IN-) ; also on sheet 77
VDD_MCU_RAM_0V85_IN+: U64.D3(IN+) ; also on sheet 76
VDD_MCU_RAM_0V85_IN-: U64.D1(BUS) U64.D2(IN-) ; also on sheet 76
VDD_PHYCORE_0V8_IN+: U198.D3(IN+) ; also on sheet 76
VDD_PHYCORE_0V8_IN-: U198.D1(BUS) U198.D2(IN-) ; also on sheet 76
VDD_SD_DV_IN+: U214.D3(IN+) ; also on sheet 77
VDD_SD_DV_IN-: U214.D1(BUS) U214.D2(IN-) ; also on sheet 77
CAN_STB: R709.1 U152.8(STB) ; also on sheet 30 38
CORE_0V8_IN+: U188.D3(IN+) ; also on sheet 76
CORE_0V8_IN-: U188.D1(BUS) U188.D2(IN-) ; also on sheet 76
CORE_RAM_0V85_IN+: U207.D3(IN+) ; also on sheet 76
CORE_RAM_0V85_IN-: U207.D1(BUS) U207.D2(IN-) ; also on sheet 76
CPU_AVS_IN+: U194.D3(IN+) ; also on sheet 76
CPU_AVS_IN-: U194.D1(BUS) U194.D2(IN-) ; also on sheet 76
DLL_0V8_IN+: U99.D3(IN+) ; also on sheet 77
DLL_0V8_IN-: U99.D1(BUS) U99.D2(IN-) ; also on sheet 77
EN_TPS61240: R662.2 U139.4(EN)
L_TPS61240_1: L36.2 U139.5(L)
MCAN4_H: J45.1 R720.1 U152.7(CANH)
MCAN4_L: J45.3 R719.2 U152.6(CANL)
MCAN4_RX: J36.2 R682.1 ; also on sheet 19
MCAN4_T: C541.1 R719.1 R720.2
MCAN4_TX: J36.1 U152.1(TXD) ; also on sheet 19
MCAN16_H: J46.1 R722.1 U153.7(CANH)
MCAN16_L: J46.3 R721.2 U153.6(CANL)
MCAN16_RX: R683.1 ; also on sheet 20
MCAN16_STB: R710.2 U153.8(STB)
MCAN16_T: C542.1 R721.1 R722.2
MCAN16_TX: U153.1(TXD) ; also on sheet 20
MCU_0V85_IN+: U61.D3(IN+) ; also on sheet 76
MCU_0V85_IN-: U61.D1(BUS) U61.D2(IN-) ; also on sheet 76
MCU_1V8+: U119.D3(IN+) ; also on sheet 76
MCU_1V8-: U119.D1(BUS) U119.D2(IN-) ; also on sheet 76
MCUIO_1V8_IN+: U105.D3(IN+) ; also on sheet 76
MCUIO_1V8_IN-: U105.D1(BUS) U105.D2(IN-) ; also on sheet 76
MCUIO_3V3_IN+: U114.D3(IN+) ; also on sheet 76
MCUIO_3V3_IN-: U114.D1(BUS) U114.D2(IN-) ; also on sheet 76
PHYIO_1V8_IN+: U192.D3(IN+) ; also on sheet 76
PHYIO_1V8_IN-: U192.D1(BUS) U192.D2(IN-) ; also on sheet 76
PLL_1V8_IN+: U225.D3(IN+) ; also on sheet 76
PLL_1V8_IN-: U225.D1(BUS) U225.D2(IN-) ; also on sheet 76
PM1_SCL: U61.A1(SCL) U64.A1(SCL) U105.A1(SCL) U114.A1(SCL) U114.B3(A0) U119.A1(SCL) U188.A1(SCL) U207.A1(SCL) U231.A1(SCL) U231.B3(A0) ; also on sheet 47 63 73 76
PM1_SCL_1: U84.A1(SCL) U185.A1(SCL) U185.C3(A1) U192.A1(SCL) U192.C3(A1) U194.A1(SCL) U198.A1(SCL) U198.B3(A0) U225.A1(SCL) U225.C3(A1) U230.A1(SCL) U235.A1(SCL) U235.B3(A0) U235.C3(A1) ; also on sheet 76
PM1_SDA: U61.A2(SDA) U64.A2(SDA) U105.A2(SDA) U114.A2(SDA) U119.A2(SDA) U119.B3(A0) U188.A2(SDA) U207.A2(SDA) U207.B3(A0) U231.A2(SDA) ; also on sheet 47 63 73 76
PM1_SDA_1: U84.A2(SDA) U84.B3(A0) U84.C3(A1) U185.A2(SDA) U185.B3(A0) U192.A2(SDA) U194.A2(SDA) U194.C3(A1) U198.A2(SDA) U198.C3(A1) U225.A2(SDA) U230.A2(SDA) U230.C3(A1) U235.A2(SDA) ; also on sheet 76
PM2_SCL: U57.A1(SCL) U93.A1(SCL) U116.A1(SCL) U116.B3(A0) U121.A1(SCL) U129.A1(SCL) U129.B3(A0) U204.A1(SCL) U214.A1(SCL) U219.A1(SCL) ; also on sheet 47 62 63 73 77
PM2_SCL_1: U31.A1(SCL) U31.B3(A0) U31.C3(A1) U99.A1(SCL) U99.C3(A1) U171.A1(SCL) U171.C3(A1) U210.A1(SCL) U211.A1(SCL) U211.C3(A1) U222.A1(SCL) U223.A1(SCL) U223.B3(A0) U238.A1(SCL) ; also on sheet 77
PM2_SDA: U57.A2(SDA) U93.A2(SDA) U116.A2(SDA) U121.A2(SDA) U121.B3(A0) U129.A2(SDA) U204.A2(SDA) U214.A2(SDA) U214.B3(A0) U219.A2(SDA) ; also on sheet 47 62 63 73 77
PM2_SDA_1: U31.A2(SDA) U99.A2(SDA) U99.B3(A0) U171.A2(SDA) U210.A2(SDA) U210.C3(A1) U211.A2(SDA) U222.A2(SDA) U222.C3(A1) U223.A2(SDA) U223.C3(A1) U238.A2(SDA) U238.B3(A0) U238.C3(A1) ; also on sheet 77
R_MCAN4_RXD: R682.2 U152.4(RXD)
R_MCAN16_RXD: R683.2 U153.4(RXD)
USB_3V3_IN+: U185.D3(IN+) ; also on sheet 76
USB_3V3_IN-: U185.D1(BUS) U185.D2(IN-) ; also on sheet 76
VSYS_3V3: U64.B3(A0) U93.C3(A1) U105.C3(A1) U116.C3(A1) U121.C3(A1) U188.B3(A0) U188.C3(A1) U192.B3(A0) U207.C3(A1) U211.B3(A0) U222.B3(A0) U230.B3(A0) U231.C3(A1) ; also on sheet 22 23 35 36 40 47 49 62 63 65 66 67 68 69 73 75 76 77
VSYS_3V3_1: U105.B1(VS) U114.B1(VS) U188.B1(VS) U204.B1(VS) U204.B3(A0) U204.C3(A1) U207.B1(VS) U214.B1(VS) U219.B1(VS) U219.B3(A0) U231.B1(VS) ; also on sheet 76 77
VSYS_3V3_2: U185.B1(VS) U192.B1(VS) U194.B1(VS) U198.B1(VS) U222.B1(VS) U225.B1(VS) U230.B1(VS) U235.B1(VS) ; also on sheet 76 77
VSYS_3V3_3: U57.B1(VS) U61.B1(VS) U64.B1(VS) U93.B1(VS) U116.B1(VS) U119.B1(VS) U121.B1(VS) U129.B1(VS) ; also on sheet 76 77
VSYS_3V3_4: U31.B1(VS) U84.B1(VS) U99.B1(VS) U171.B1(VS) U210.B1(VS) U211.B1(VS) U223.B1(VS) U238.B1(VS) ; also on sheet 76 77
VSYS_3V3_IN+: U171.D3(IN+) ; also on sheet 77
VSYS_3V3_IN-: U171.D1(BUS) U171.D2(IN-) ; also on sheet 77
VSYS_5V0: C497.2 U152.3(VCC) ; also on sheet 20 30 31 50 52 59 65 68 72 82 83 84
VSYS_5V0_IN+: U223.D3(IN+) ; also on sheet 77
VSYS_5V0_IN-: U223.D1(BUS) U223.D2(IN-) ; also on sheet 77
VSYS_GPIORET_5V0: C453.1 C454.1 C498.2 TP238.1(TP) U139.2(VOUT) U139.3(FB) U153.3(VCC)
VSYS_GPIORET_IO_3V3_IN+: U230.D3(IN+) ; also on sheet 76
VSYS_GPIORET_IO_3V3_IN-: U230.D1(BUS) U230.D2(IN-) ; also on sheet 76
VSYS_IO_1V8_IN+: U210.D3(IN+) ; also on sheet 77
VSYS_IO_1V8_IN-: U210.D1(BUS) U210.D2(IN-) ; also on sheet 77
VSYS_IO_3V3: C535.1 R709.2 U152.5(VIO) ; also on sheet 18 20 22 24 29 30 31 32 33 35 36 37 38 40 41 42 43 45 46 48 50 51 53 56 57 58 59 60 61 65 66 68 75 82
VSYS_IO_3V3_IN+: U222.D3(IN+) ; also on sheet 77
VSYS_IO_3V3_IN-: U222.D1(BUS) U222.D2(IN-) ; also on sheet 77
VSYS_MCUIO_1V8_IN+: U121.D3(IN+) ; also on sheet 77
VSYS_MCUIO_1V8_IN-: U121.D1(BUS) U121.D2(IN-) ; also on sheet 77
VSYS_MCUIO_3V3_IN+: U116.D3(IN+) ; also on sheet 77
VSYS_MCUIO_3V3_IN-: U116.D1(BUS) U116.D2(IN-) ; also on sheet 77
VSYS_VDDSHV2: C536.1 R662.1 U153.5(VIO) ; also on sheet 18 20

Not connected (* = marked no-connect by the designer): U31 A3(ALERT)* B2(NC1)* C2(NC2)*; U57 A3(ALERT)* B2(NC1)* C2(NC2)*; U61 A3(ALERT)* B2(NC1)* C2(NC2)*; U64 A3(ALERT)* B2(NC1)* C2(NC2)*; U84 A3(ALERT)* B2(NC1)* C2(NC2)*; U93 A3(ALERT)* B2(NC1)* C2(NC2)*; U99 A3(ALERT)* B2(NC1)* C2(NC2)*; U105 A3(ALERT)* B2(NC1)* C2(NC2)*; U114 A3(ALERT)* B2(NC1)* C2(NC2)*; U116 A3(ALERT)* B2(NC1)* C2(NC2)*; U119 A3(ALERT)* B2(NC1)* C2(NC2)*; U121 A3(ALERT)* B2(NC1)* C2(NC2)*; U129 A3(ALERT)* B2(NC1)* C2(NC2)*; U171 A3(ALERT)* B2(NC1)* C2(NC2)*; U185 A3(ALERT)* B2(NC1)* C2(NC2)*; U188 A3(ALERT)* B2(NC1)* C2(NC2)*; U192 A3(ALERT)* B2(NC1)* C2(NC2)*; U194 A3(ALERT)* B2(NC1)* C2(NC2)*; U198 A3(ALERT)* B2(NC1)* C2(NC2)*; U204 A3(ALERT)* B2(NC1)* C2(NC2)*; U207 A3(ALERT)* B2(NC1)* C2(NC2)*; U210 A3(ALERT)* B2(NC1)* C2(NC2)*; U211 A3(ALERT)* B2(NC1)* C2(NC2)*; U214 A3(ALERT)* B2(NC1)* C2(NC2)*; U219 A3(ALERT)* B2(NC1)* C2(NC2)*; U222 A3(ALERT)* B2(NC1)* C2(NC2)*; U223 A3(ALERT)* B2(NC1)* C2(NC2)*; U225 A3(ALERT)* B2(NC1)* C2(NC2)*; U230 A3(ALERT)* B2(NC1)* C2(NC2)*; U231 A3(ALERT)* B2(NC1)* C2(NC2)*; U235 A3(ALERT)* B2(NC1)* C2(NC2)*; U238 A3(ALERT)* B2(NC1)* C2(NC2)*

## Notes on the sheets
sheet 78
- Note:  The design supports current/voltage measurements
  using either INA226 or INA231. The EVM will be assembled
  with either INA226 or INA231, but not both
  (implemented via dual or stacked PCB footprint).
  These two INA devices are register compatible–
  so functionality and performance should not be impacted with either INA
- CURRENT MONITORS - INA231
- I2C ADDRESS: 100-0011 (0x43)
- I2C ADDRESS: 100-0010 (0x42)
- I2C ADDRESS: 100-0000 (0x40)
- Reserved for future
- I2C ADDRESS: 100-0110 (0x46)
- I2C ADDRESS: 100-0101 (0x45)
- I2C ADDRESS: 100-0100 (0x44)
- Reserved for future
- I2C ADDRESS: 100-1100 (0x4C)
- I2C ADDRESS: 100-0111 (0x47)
- I2C ADDRESS: 100-1000 (0x48)
- I2C ADDRESS: 100-1101 (0x4D)
- I2C ADDRESS: 100-1111 (0x4F)
- I2C ADDRESS: 100-1110 (0x4E)
- Reserved for future
- I2C ADDRESS: 100-1001 (0x49)
- I2C ADDRESS: 100-1011 (0x4B)
- I2C ADDRESS: 100-1010 (0x4A)
- I2C ADDRESS: 100-0001 (0x41)
sheet 79
- Note:  The design supports current/voltage measurements
  using either INA226 or INA231. The EVM will be assembled
  with either INA226 or INA231, but not both
  (implemented via dual or stacked PCB footprint).
  These two INA devices are register compatible–
  so functionality and performance should not be impacted with either INA
- CURRENT MONITORS - INA231
- I2C ADDRESS: 100-0000 (0x40)
- I2C ADDRESS: 100-0001 (0x41)
- I2C ADDRESS: 100-0010 (0x42)
- Reserved for future
- I2C ADDRESS: 100-0011 (0x43)
- I2C ADDRESS: 100-0100 (0x44)
- I2C ADDRESS: 100-0101 (0x45)
- I2C ADDRESS: 100-0111 (0x47)
- I2C ADDRESS: 100-0110 (0x46)
- I2C ADDRESS: 100-1000 (0x48)
- I2C ADDRESS: 100-1010 (0x4A)
- I2C ADDRESS: 100-1001 (0x49)
- I2C ADDRESS: 100-1011 (0x4B)
- I2C ADDRESS: 100-1101 (0x4D)
- I2C ADDRESS: 100-1100 (0x4C)
- I2C ADDRESS: 100-1110 (0x4E)
- I2C ADDRESS: 100-1111 (0x4F)
sheet 80
- HARDWARE SCHEMATICS
- STANDOFFs
- SCREWS
- FIDUCIALS
- ASSEMBLY NOTES
- 1. All MSL components should be baked as per JEDEC standard.
  2. PCB should be baked at 120 degree for 8 hours.
  3. Board assembly must comply with workmanship standards.
  IPC-A-610 Class 2, unless otherwise specified.
  4. These assemblies are ESD sensitive, ESD precautions
  shall be observed.
  5. These assemblies must be clean and free from flux and
  all contaminants. Use of no clean flux is not acceptable.
  6. Provide serial numbers to the assembled boards for identification.
  7. The assembled board are wrapped in ESD Covers(individual) and
  packed securely before shipment.
- RUBBER FEET
- BARE PCB
- SCREW FOR FAN ASSEMBLY
- LOGOs
- Texas Intruments
- For Evaluation only; not FCC approved for resale
- WEEE Mark
- CE Mark
- HEAT SINK
- SOCKET
- PROCESSOR
- FAN
- CRIMP PIN
- CONN HOUSING
- LABELS
- EVM Orderable No.
- Board Serial No.
- Orderable Part Numbers
- Assembly Revision.
- Variant
- Label Text
- 001:Soldered GP SoC
- J742S2XG01EVM
- J742S2XH01EVM
- 002:Soldered HS SoC
- 003:Socketed SoC
- J742S2XS01EVM
sheet 81
- VSYS_GPIORET_5V0 GENERATION
- CAN TRANSCEIVER
- Note: Booster convertor required for EVM due to system 5V
  supply shutting down in retention mode
- 120E
- 120E
